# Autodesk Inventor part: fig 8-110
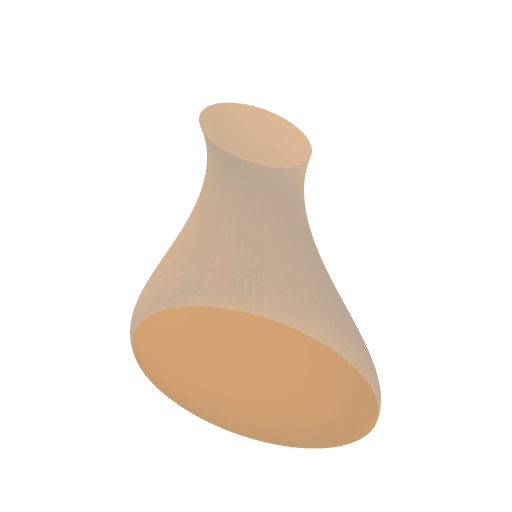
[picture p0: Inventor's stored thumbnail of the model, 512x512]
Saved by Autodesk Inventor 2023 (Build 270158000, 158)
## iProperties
Created: 2004-05
Part Number: fig 8-110
Document SubType Name: Modeling
Designer: CADCIM Technologies
Manufacturer: Standard
Standards Organization: Custom
Density: 1 g/cm^3
Material: Generic
Appearance: Default
Author: CADCIM Technologies
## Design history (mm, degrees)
sketch "Sketch4"
  geometry: 1 further point; 1 other entity
  constraints: 2 other
workplane "Work Plane2"
sketch "Sketch5"
  geometry: 1 further point; 1 other entity
  constraints: 2 other
feature "LoftSrf1" sketch "Sketch5" dims "d4" = 20, "d5" = 110 deg, "d6" = 40, "d7" = 70 deg
patch "Boundary Patch1" dims "d8" = 0, "d9" = 0
patch "Boundary Patch2" dims "d10" = 0, "d11" = 0
patch "Boundary Patch3" dims "d12" = 0, "d13" = 0
body "Srf1"
body "Srf2"
body "Srf3"
body "Srf4"
other parameters: "d3" = 33.5
